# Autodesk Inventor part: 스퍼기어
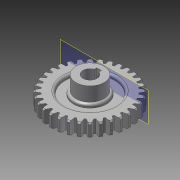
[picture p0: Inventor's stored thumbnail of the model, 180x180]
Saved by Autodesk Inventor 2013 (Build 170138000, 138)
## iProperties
Created: 2010-04
Part Number: 스퍼기어
Material: 강
Document SubType Name: Modeling
Designer: KYOUNG IL JANG
Categories: <?xml version="1.0" encoding="UTF-16"?> <MemberInstance><Categories><FamilyTemplate><FamilyTemplateParameter ValueType="xs:double" Id="1" ObjectReferenceKey="da
Density: 7.85 g/cm^3
Mass: 256.791 g
Surface Area: 133.154 cm^2
Volume: 32.7123 cm^3
CustomPartVersion: 1
Author: 진현석
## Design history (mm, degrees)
sketch "Sketch1"
  geometry: C1 r 34 at (0, 0)
  constraints: 1 centre point
  dimensions: "d0" = 68 diameter of C1 (= da_da)
extrude "Extrusion1" new body sketch "Sketch1" distance "d1" = 11 (= da_b); taper "d2" = 0 deg
chamfer "모따기2" distance "d62" = 1; stored, may be unused: second distance "d63" = 2, angle "d64" = 45 deg
workplane "Work Plane2"
feature "피치 지름" dims "d4" = 10, "d5" = 0
workplane "Work Plane8"
workplane "Work Plane9"
feature "스퍼 기어" dims "da_b" = 11, "da_d" = 64, "da_aw" = 96, "da_da" = 68, "da_df" = 59, "da_dw" = 64, angle "da_beta" = 0 deg, "da_lefttooth" = 0, "da_righttooth" = 0
sketch "스케치5"
  geometry: L1 (-2, 5.657)-(2, 5.657); L2 (2, 5.657)-(2, 7.8); L3 (2, 7.8)-(-2, 7.8); L4 (-2, 7.8)-(-2, 5.657); A1 r 6 centre (0, 0) between (-2, 5.657) and (2, 5.657); 1 further point
  constraints: 8 end point, 2 parallel, 2 point on circle, 1 centre point, 1 coincident, 1 horizontal, 1 perpendicular
  dimensions: "d65" = 12 diameter of A1; "d66" = 4 distance of L2.end L3.end; "d67" = 13.8 dimension on A1 L3
extrude "돌출4" cut sketch "스케치5" stored distance "d68" = 10; taper "d69" = 0 deg
sketch "스케치6"
  geometry: L1 (7.8, 0)-(7.8, 11) reference; L2 (7.8, 11)-(33, 11) reference; L3 (33, 11)-(34, 10) reference; L4 (34, 10)-(34, 1) reference; L5 (34, 1)-(33, 0) reference; L6 (33, 0)-(7.8, 0) reference; L7 (-6, 11)-(-6, 0) reference; L8 (-6, 0)-(-33, 0) reference; L9 (-33, 0)-(-34, 1) reference; L10 (-34, 1)-(-34, 10) reference; L11 (-34, 10)-(-33, 11) reference; L12 (-33, 11)-(-6, 11) reference; L13 (-21, 11)-(-14, 11); L14 (-14, 11)-(-14, 8); L15 (-14, 8)-(-21, 8); L16 (-21, 8)-(-21, 11); L17 (-21, 0)-(-14, 0); L18 (-14, 0)-(-14, 3); L19 (-14, 3)-(-21, 3); L20 (-21, 3)-(-21, 0); L21 (0, -2.202)-(0, 13.202) reference; 1 further point
  constraints: 16 end point, 4 parallel, 2 equal length, 2 horizontal, 2 perpendicular, 2 point on line, 1 collinear
  dimensions: "d70" = 3 distance of L13.end L14.end; "d71" = 28 diameter of L14 L21; "d72" = 42 diameter of L16 L21
revolve "회전1" sketch "스케치6" stored, may be unused: angle "d73" = 90 deg
fillet "모깎기2" dims "d74" = 2
sketch "스케치7"
  geometry: L1 (-2, 5.657)-(-2, 7.8) reference; L2 (-2, 7.8)-(2, 7.8) reference; L3 (2, 7.8)-(2, 5.657) reference; C1 r 12 at (0, 0) reference; A1 r 6 centre (0, 0) between (-2, 5.657) and (2, 5.657) reference
extrude "돌출5" join sketch "스케치7" distance "d75" = 12; taper "d76" = 0 deg
node "작업 평면12"
sketch "스케치8"
  geometry: L1 (12, 12)-(-12, 12) reference; 2 further points
  constraints: 1 vertical alignment
  dimensions: "d77" = 6 distance from line of point (0, 6) L1
hole "구멍1" sketch "스케치8" at (0, 6) diameter "d78" = 2.459; stored, may be unused: countersink angle "d82" = 90 deg, drill point angle "d84" = 118 deg; dims "d79" = 6, "d80" = 4, "d81" = 2, "d83" = 8
body "Solid1"
sketch "Sketch2"
  geometry: C1 r 34 at (0, 0) reference; C2 r 32 at (0, 0)
  constraints: 1 centre point, 1 coincident
  dimensions: "d3" = 64 diameter of C2 (= da_dw)
body "Srf1"
node "투영된 루프1"
node "절단 모서리 투영1"
other parameters: "d16" = 96 (= da_aw), "d17" = 0, "d34" = 0.98175 (computed from da_z), "d39" = 0, "d41" = 0, "d43" = 96 (= da_aw), "d46" = 96 (= da_aw), "d47" = 0, "d48" = 0
